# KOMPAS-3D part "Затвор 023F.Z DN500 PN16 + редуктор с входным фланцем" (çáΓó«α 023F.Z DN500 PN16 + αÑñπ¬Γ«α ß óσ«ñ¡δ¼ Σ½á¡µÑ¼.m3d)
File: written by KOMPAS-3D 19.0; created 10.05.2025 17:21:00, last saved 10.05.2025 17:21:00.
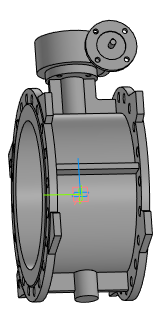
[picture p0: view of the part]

Document properties: Полное имя файла: Затвор 023F.Z DN500 PN16 + редуктор с входным фланцем.a3d

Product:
- Part/product: Затвор 023F.Z DN500 PN16 + редуктор с входным фланцем
    Масса: 314.351

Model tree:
1. Операция без истории:1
